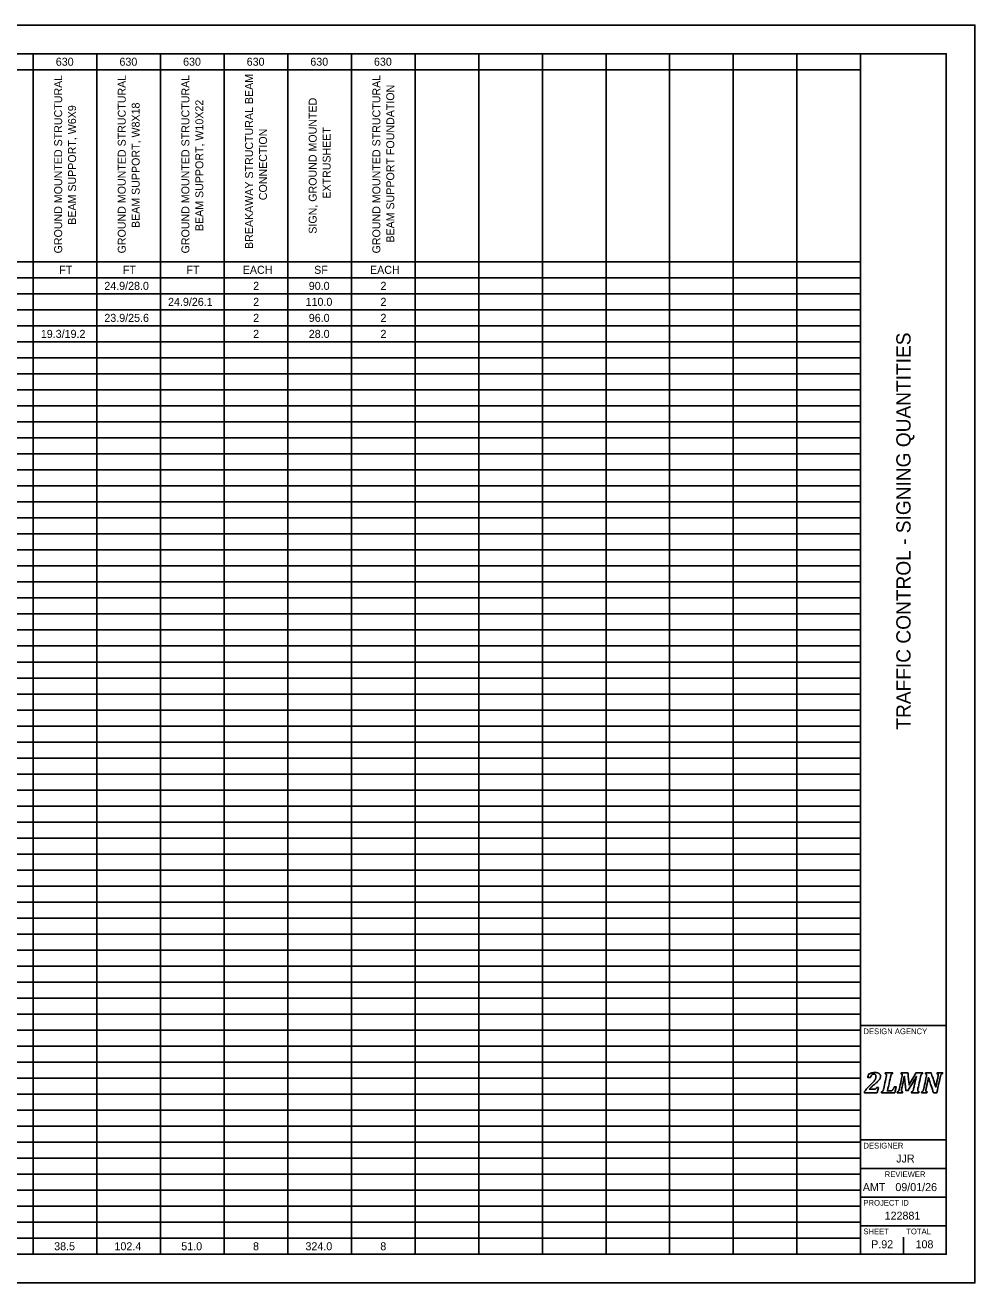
# Model space of a CAD drawing. Extents: x 0 to 34, y 0 to 22.
# Drawn here: x 17.38 to 34, y 0 to 22 of the extents above; entities that cross this region are included whole.
import ezdxf

# ---------------------------------------------------------------- set-up
doc = ezdxf.new("R2010")
doc.units = 0
for name, color, linetype in [('SH_Border', 7, 'Continuous'), ('SH_Cut_Line', 7, 'Continuous'), ('SH_Data', 7, 'Continuous'), ('SH_Text', 7, 'Continuous')]:
    doc.layers.add(name, color=color, linetype=linetype)

msp = doc.modelspace()

# ---------------------------------------------------------------- linework, layer by layer
at = {"layer": 'SH_Border'}
for p, q in [((32, 0.5), (32, 21.5)), ((32, 4.5), (33.5, 4.5)), ((32, 2.5), (33.5, 2.5)), ((32, 2), (33.5, 2)), ((32, 1.5), (33.5, 1.5)), ((32, 1), (33.5, 1))]:
    msp.add_line(p, q, dxfattribs=at)
msp.add_lwpolyline([(1.5, 21.5), (33.5, 21.5), (33.5, 0.5), (1.5, 0.5)], close=True, dxfattribs=at)
at = {"layer": 'SH_Cut_Line'}
msp.add_lwpolyline([(0, 0), (34, 0), (34, 22), (0, 22)], close=True, dxfattribs=at)
at = {"layer": 'SH_Data'}
for p, q in [((32.75, 3.5), (32.75, 3.5)), ((32.375, 0.675), (32.375, 0.675)), ((32.75, 0.5), (32.75, 0.8))]:
    msp.add_line(p, q, dxfattribs=at)
for points in [[(32.237, 3.388), (32.246, 3.388), (32.253, 3.389), (32.258, 3.39), (32.263, 3.392), (32.267, 3.394), (32.27, 3.397), (32.273, 3.401), (32.277, 3.408), (32.281, 3.417), (32.281, 3.417), (32.312, 3.417), (32.312, 3.417), (32.312, 3.417), (32.29, 3.326), (32.29, 3.326), (32.29, 3.326), (32.066, 3.326), (32.066, 3.326), (32.066, 3.326), (32.069, 3.343), (32.069, 3.343), (32.078, 3.358), (32.091, 3.375), (32.106, 3.394), (32.122, 3.412), (32.144, 3.435), (32.172, 3.462), (32.197, 3.486), (32.217, 3.506), (32.23, 3.521), (32.243, 3.537), (32.253, 3.551), (32.259, 3.566), (32.266, 3.58), (32.269, 3.595), (32.269, 3.61), (32.269, 3.622), (32.266, 3.632), (32.26, 3.64), (32.253, 3.647), (32.245, 3.65), (32.234, 3.65), (32.22, 3.65), (32.208, 3.646), (32.198, 3.636), (32.188, 3.627), (32.18, 3.613), (32.172, 3.593), (32.172, 3.593), (32.126, 3.593), (32.126, 3.593), (32.126, 3.593), (32.14, 3.654), (32.14, 3.654), (32.166, 3.663), (32.188, 3.669), (32.205, 3.673), (32.223, 3.676), (32.24, 3.678), (32.258, 3.678), (32.278, 3.678), (32.295, 3.675), (32.309, 3.669), (32.322, 3.664), (32.332, 3.656), (32.339, 3.646), (32.345, 3.637), (32.348, 3.626), (32.348, 3.613), (32.348, 3.602), (32.346, 3.591), (32.342, 3.581), (32.339, 3.571), (32.333, 3.56), (32.324, 3.549), (32.315, 3.539), (32.304, 3.526), (32.289, 3.513), (32.275, 3.499), (32.254, 3.482), (32.228, 3.46), (32.216, 3.45), (32.202, 3.438), (32.188, 3.425), (32.174, 3.412), (32.162, 3.4), (32.154, 3.391), (32.154, 3.391), (32.153, 3.388), (32.153, 3.388), (32.153, 3.388), (32.237, 3.388), (32.237, 3.388)], [(32.237, 3.388), (32.237, 3.388), (32.153, 3.388), (32.153, 3.388), (32.153, 3.388), (32.154, 3.391), (32.154, 3.391), (32.162, 3.4), (32.174, 3.412), (32.188, 3.425), (32.202, 3.438), (32.216, 3.45), (32.228, 3.46), (32.254, 3.482), (32.275, 3.499), (32.289, 3.513), (32.304, 3.526), (32.315, 3.539), (32.324, 3.549), (32.333, 3.56), (32.339, 3.571), (32.342, 3.581), (32.346, 3.591), (32.348, 3.602), (32.348, 3.613), (32.348, 3.626), (32.345, 3.637), (32.339, 3.646), (32.332, 3.656), (32.322, 3.664), (32.309, 3.669), (32.295, 3.675), (32.278, 3.678), (32.258, 3.678), (32.24, 3.678), (32.223, 3.676), (32.205, 3.673), (32.188, 3.669), (32.166, 3.663), (32.14, 3.654), (32.14, 3.654), (32.126, 3.593), (32.126, 3.593), (32.126, 3.593), (32.172, 3.593), (32.172, 3.593), (32.18, 3.613), (32.188, 3.627), (32.198, 3.636), (32.208, 3.646), (32.22, 3.65), (32.234, 3.65), (32.245, 3.65), (32.253, 3.647), (32.26, 3.64), (32.266, 3.632), (32.269, 3.622), (32.269, 3.61), (32.269, 3.595), (32.266, 3.58), (32.259, 3.566), (32.253, 3.551), (32.243, 3.537), (32.23, 3.521), (32.217, 3.506), (32.197, 3.486), (32.172, 3.462), (32.144, 3.435), (32.122, 3.412), (32.106, 3.394), (32.091, 3.375), (32.078, 3.358), (32.069, 3.343), (32.069, 3.343), (32.066, 3.326), (32.066, 3.326), (32.066, 3.326), (32.29, 3.326), (32.29, 3.326), (32.29, 3.326), (32.312, 3.417), (32.312, 3.417), (32.312, 3.417), (32.281, 3.417), (32.281, 3.417), (32.277, 3.408), (32.273, 3.401), (32.27, 3.397), (32.267, 3.394), (32.263, 3.392), (32.258, 3.39), (32.253, 3.389), (32.246, 3.388), (32.237, 3.388)], [(32.518, 3.356), (32.527, 3.356), (32.533, 3.357), (32.538, 3.358), (32.542, 3.36), (32.546, 3.362), (32.55, 3.365), (32.554, 3.368), (32.558, 3.372), (32.562, 3.377), (32.567, 3.382), (32.571, 3.388), (32.576, 3.397), (32.58, 3.405), (32.585, 3.415), (32.589, 3.427), (32.589, 3.427), (32.624, 3.427), (32.624, 3.427), (32.624, 3.427), (32.598, 3.326), (32.598, 3.326), (32.598, 3.326), (32.365, 3.326), (32.365, 3.326), (32.365, 3.326), (32.369, 3.343), (32.369, 3.343), (32.376, 3.345), (32.381, 3.348), (32.385, 3.351), (32.389, 3.355), (32.392, 3.36), (32.395, 3.366), (32.398, 3.373), (32.4, 3.382), (32.403, 3.395), (32.403, 3.395), (32.449, 3.605), (32.449, 3.605), (32.452, 3.615), (32.453, 3.625), (32.453, 3.635), (32.453, 3.642), (32.451, 3.647), (32.448, 3.651), (32.444, 3.654), (32.439, 3.656), (32.432, 3.657), (32.432, 3.657), (32.435, 3.674), (32.435, 3.674), (32.435, 3.674), (32.563, 3.674), (32.563, 3.674), (32.563, 3.674), (32.559, 3.657), (32.559, 3.657), (32.552, 3.655), (32.547, 3.652), (32.543, 3.649), (32.539, 3.645), (32.536, 3.64), (32.533, 3.634), (32.531, 3.627), (32.528, 3.618), (32.525, 3.605), (32.525, 3.605), (32.47, 3.356), (32.47, 3.356), (32.47, 3.356), (32.518, 3.356), (32.518, 3.356)], [(32.518, 3.356), (32.518, 3.356), (32.47, 3.356), (32.47, 3.356), (32.47, 3.356), (32.525, 3.605), (32.525, 3.605), (32.528, 3.618), (32.531, 3.627), (32.533, 3.634), (32.536, 3.64), (32.539, 3.645), (32.543, 3.649), (32.547, 3.652), (32.552, 3.655), (32.559, 3.657), (32.559, 3.657), (32.563, 3.674), (32.563, 3.674), (32.563, 3.674), (32.435, 3.674), (32.435, 3.674), (32.435, 3.674), (32.432, 3.657), (32.432, 3.657), (32.439, 3.656), (32.444, 3.654), (32.448, 3.651), (32.451, 3.647), (32.453, 3.642), (32.453, 3.635), (32.453, 3.625), (32.452, 3.615), (32.449, 3.605), (32.449, 3.605), (32.403, 3.395), (32.403, 3.395), (32.4, 3.382), (32.398, 3.373), (32.395, 3.366), (32.392, 3.36), (32.389, 3.355), (32.385, 3.351), (32.381, 3.348), (32.376, 3.345), (32.369, 3.343), (32.369, 3.343), (32.365, 3.326), (32.365, 3.326), (32.365, 3.326), (32.598, 3.326), (32.598, 3.326), (32.598, 3.326), (32.624, 3.427), (32.624, 3.427), (32.624, 3.427), (32.589, 3.427), (32.589, 3.427), (32.585, 3.415), (32.58, 3.405), (32.576, 3.397), (32.571, 3.388), (32.567, 3.382), (32.562, 3.377), (32.558, 3.372), (32.554, 3.368), (32.55, 3.365), (32.546, 3.362), (32.542, 3.36), (32.538, 3.358), (32.533, 3.357), (32.527, 3.356), (32.518, 3.356)], [(32.829, 3.674), (32.829, 3.674), (32.849, 3.461), (32.849, 3.461), (32.849, 3.461), (32.969, 3.674), (32.969, 3.674), (32.969, 3.674), (33.087, 3.674), (33.087, 3.674), (33.087, 3.674), (33.084, 3.657), (33.084, 3.657), (33.077, 3.655), (33.071, 3.652), (33.067, 3.649), (33.064, 3.645), (33.06, 3.64), (33.058, 3.634), (33.055, 3.627), (33.052, 3.618), (33.05, 3.605), (33.05, 3.605), (33.003, 3.395), (33.003, 3.395), (33.002, 3.39), (33.002, 3.387), (33.001, 3.384), (33.001, 3.382), (33.001, 3.379), (33, 3.376), (33, 3.373), (33, 3.369), (33, 3.365), (33, 3.358), (33.002, 3.353), (33.005, 3.349), (33.008, 3.346), (33.014, 3.344), (33.021, 3.343), (33.021, 3.343), (33.018, 3.326), (33.018, 3.326), (33.018, 3.326), (32.89, 3.326), (32.89, 3.326), (32.89, 3.326), (32.893, 3.343), (32.893, 3.343), (32.9, 3.345), (32.906, 3.348), (32.91, 3.351), (32.914, 3.355), (32.917, 3.36), (32.919, 3.366), (32.922, 3.373), (32.925, 3.382), (32.928, 3.395), (32.928, 3.395), (32.951, 3.502), (32.951, 3.502), (32.954, 3.513), (32.957, 3.529), (32.962, 3.548), (32.967, 3.568), (32.972, 3.588), (32.978, 3.609), (32.978, 3.609), (32.973, 3.609), (32.973, 3.609), (32.965, 3.594), (32.957, 3.579), (32.948, 3.563), (32.948, 3.563), (32.833, 3.364), (32.833, 3.364), (32.833, 3.364), (32.792, 3.364), (32.792, 3.364), (32.792, 3.364), (32.775, 3.518), (32.775, 3.518), (32.773, 3.537), (32.772, 3.554), (32.77, 3.569), (32.769, 3.583), (32.768, 3.597), (32.768, 3.611), (32.768, 3.611), (32.764, 3.611), (32.764, 3.611), (32.761, 3.596), (32.758, 3.578), (32.755, 3.558), (32.751, 3.538), (32.747, 3.521), (32.744, 3.507), (32.744, 3.507), (32.72, 3.395), (32.72, 3.395), (32.719, 3.39), (32.718, 3.387), (32.718, 3.384), (32.717, 3.382), (32.717, 3.379), (32.717, 3.376), (32.717, 3.373), (32.716, 3.369), (32.716, 3.365), (32.716, 3.358), (32.718, 3.353), (32.721, 3.349), (32.725, 3.346), (32.73, 3.344), (32.738, 3.343), (32.738, 3.343), (32.734, 3.326), (32.734, 3.326), (32.734, 3.326), (32.641, 3.326), (32.641, 3.326), (32.641, 3.326), (32.644, 3.343), (32.644, 3.343), (32.651, 3.345), (32.657, 3.348), (32.661, 3.351), (32.665, 3.355), (32.668, 3.36), (32.67, 3.366), (32.673, 3.373), (32.676, 3.382), (32.679, 3.395), (32.679, 3.395), (32.725, 3.605), (32.725, 3.605), (32.727, 3.615), (32.728, 3.625), (32.728, 3.635), (32.728, 3.642), (32.727, 3.647), (32.723, 3.651), (32.72, 3.654), (32.715, 3.656), (32.707, 3.657), (32.707, 3.657), (32.711, 3.674), (32.711, 3.674), (32.711, 3.674), (32.829, 3.674), (32.829, 3.674)], [(32.829, 3.674), (32.829, 3.674), (32.711, 3.674), (32.711, 3.674), (32.711, 3.674), (32.707, 3.657), (32.707, 3.657), (32.715, 3.656), (32.72, 3.654), (32.723, 3.651), (32.727, 3.647), (32.728, 3.642), (32.728, 3.635), (32.728, 3.625), (32.727, 3.615), (32.725, 3.605), (32.725, 3.605), (32.679, 3.395), (32.679, 3.395), (32.676, 3.382), (32.673, 3.373), (32.67, 3.366), (32.668, 3.36), (32.665, 3.355), (32.661, 3.351), (32.657, 3.348), (32.651, 3.345), (32.644, 3.343), (32.644, 3.343), (32.641, 3.326), (32.641, 3.326), (32.641, 3.326), (32.734, 3.326), (32.734, 3.326), (32.734, 3.326), (32.738, 3.343), (32.738, 3.343), (32.73, 3.344), (32.725, 3.346), (32.721, 3.349), (32.718, 3.353), (32.716, 3.358), (32.716, 3.365), (32.716, 3.369), (32.717, 3.373), (32.717, 3.376), (32.717, 3.379), (32.717, 3.382), (32.718, 3.384), (32.718, 3.387), (32.719, 3.39), (32.72, 3.395), (32.72, 3.395), (32.744, 3.507), (32.744, 3.507), (32.747, 3.521), (32.751, 3.538), (32.755, 3.558), (32.758, 3.578), (32.761, 3.596), (32.764, 3.611), (32.764, 3.611), (32.768, 3.611), (32.768, 3.611), (32.768, 3.597), (32.769, 3.583), (32.77, 3.569), (32.772, 3.554), (32.773, 3.537), (32.775, 3.518), (32.775, 3.518), (32.792, 3.364), (32.792, 3.364), (32.792, 3.364), (32.833, 3.364), (32.833, 3.364), (32.833, 3.364), (32.948, 3.563), (32.948, 3.563), (32.957, 3.579), (32.965, 3.594), (32.973, 3.609), (32.973, 3.609), (32.978, 3.609), (32.978, 3.609), (32.972, 3.588), (32.967, 3.568), (32.962, 3.548), (32.957, 3.529), (32.954, 3.513), (32.951, 3.502), (32.951, 3.502), (32.928, 3.395), (32.928, 3.395), (32.925, 3.382), (32.922, 3.373), (32.919, 3.366), (32.917, 3.36), (32.914, 3.355), (32.91, 3.351), (32.906, 3.348), (32.9, 3.345), (32.893, 3.343), (32.893, 3.343), (32.89, 3.326), (32.89, 3.326), (32.89, 3.326), (33.018, 3.326), (33.018, 3.326), (33.018, 3.326), (33.021, 3.343), (33.021, 3.343), (33.014, 3.344), (33.008, 3.346), (33.005, 3.349), (33.002, 3.353), (33, 3.358), (33, 3.365), (33, 3.369), (33, 3.373), (33, 3.376), (33.001, 3.379), (33.001, 3.382), (33.001, 3.384), (33.002, 3.387), (33.002, 3.39), (33.003, 3.395), (33.003, 3.395), (33.05, 3.605), (33.05, 3.605), (33.052, 3.618), (33.055, 3.627), (33.058, 3.634), (33.06, 3.64), (33.064, 3.645), (33.067, 3.649), (33.071, 3.652), (33.077, 3.655), (33.084, 3.657), (33.084, 3.657), (33.087, 3.674), (33.087, 3.674), (33.087, 3.674), (32.969, 3.674), (32.969, 3.674), (32.969, 3.674), (32.849, 3.461), (32.849, 3.461), (32.849, 3.461), (32.829, 3.674), (32.829, 3.674)], [(33.137, 3.674), (33.137, 3.674), (33.234, 3.674), (33.234, 3.674), (33.234, 3.674), (33.283, 3.53), (33.283, 3.53), (33.296, 3.49), (33.307, 3.456), (33.315, 3.426), (33.315, 3.426), (33.318, 3.426), (33.318, 3.426), (33.323, 3.455), (33.329, 3.488), (33.337, 3.523), (33.337, 3.523), (33.355, 3.605), (33.355, 3.605), (33.357, 3.615), (33.358, 3.625), (33.358, 3.635), (33.358, 3.642), (33.357, 3.647), (33.353, 3.651), (33.35, 3.654), (33.345, 3.656), (33.337, 3.657), (33.337, 3.657), (33.341, 3.674), (33.341, 3.674), (33.341, 3.674), (33.434, 3.674), (33.434, 3.674), (33.434, 3.674), (33.431, 3.657), (33.431, 3.657), (33.424, 3.655), (33.418, 3.652), (33.414, 3.649), (33.41, 3.645), (33.407, 3.64), (33.405, 3.634), (33.402, 3.627), (33.399, 3.618), (33.396, 3.605), (33.396, 3.605), (33.335, 3.326), (33.335, 3.326), (33.335, 3.326), (33.277, 3.326), (33.277, 3.326), (33.277, 3.326), (33.216, 3.504), (33.216, 3.504), (33.211, 3.518), (33.207, 3.531), (33.204, 3.543), (33.2, 3.556), (33.195, 3.571), (33.19, 3.59), (33.19, 3.59), (33.186, 3.59), (33.186, 3.59), (33.185, 3.579), (33.182, 3.563), (33.179, 3.543), (33.175, 3.523), (33.17, 3.501), (33.165, 3.478), (33.165, 3.478), (33.147, 3.395), (33.147, 3.395), (33.146, 3.39), (33.145, 3.387), (33.145, 3.384), (33.144, 3.382), (33.144, 3.379), (33.144, 3.376), (33.143, 3.373), (33.143, 3.369), (33.143, 3.365), (33.143, 3.358), (33.145, 3.353), (33.148, 3.349), (33.152, 3.346), (33.157, 3.344), (33.164, 3.343), (33.164, 3.343), (33.161, 3.326), (33.161, 3.326), (33.161, 3.326), (33.067, 3.326), (33.067, 3.326), (33.067, 3.326), (33.071, 3.343), (33.071, 3.343), (33.078, 3.345), (33.083, 3.348), (33.087, 3.351), (33.091, 3.355), (33.094, 3.36), (33.097, 3.366), (33.1, 3.373), (33.102, 3.382), (33.105, 3.395), (33.105, 3.395), (33.151, 3.605), (33.151, 3.605), (33.154, 3.615), (33.155, 3.625), (33.155, 3.635), (33.155, 3.642), (33.153, 3.647), (33.15, 3.651), (33.146, 3.654), (33.141, 3.656), (33.134, 3.657), (33.134, 3.657), (33.137, 3.674), (33.137, 3.674)], [(33.137, 3.674), (33.137, 3.674), (33.134, 3.657), (33.134, 3.657), (33.141, 3.656), (33.146, 3.654), (33.15, 3.651), (33.153, 3.647), (33.155, 3.642), (33.155, 3.635), (33.155, 3.625), (33.154, 3.615), (33.151, 3.605), (33.151, 3.605), (33.105, 3.395), (33.105, 3.395), (33.102, 3.382), (33.1, 3.373), (33.097, 3.366), (33.094, 3.36), (33.091, 3.355), (33.087, 3.351), (33.083, 3.348), (33.078, 3.345), (33.071, 3.343), (33.071, 3.343), (33.067, 3.326), (33.067, 3.326), (33.067, 3.326), (33.161, 3.326), (33.161, 3.326), (33.161, 3.326), (33.164, 3.343), (33.164, 3.343), (33.157, 3.344), (33.152, 3.346), (33.148, 3.349), (33.145, 3.353), (33.143, 3.358), (33.143, 3.365), (33.143, 3.369), (33.143, 3.373), (33.144, 3.376), (33.144, 3.379), (33.144, 3.382), (33.145, 3.384), (33.145, 3.387), (33.146, 3.39), (33.147, 3.395), (33.147, 3.395), (33.165, 3.478), (33.165, 3.478), (33.17, 3.501), (33.175, 3.523), (33.179, 3.543), (33.182, 3.563), (33.185, 3.579), (33.186, 3.59), (33.186, 3.59), (33.19, 3.59), (33.19, 3.59), (33.195, 3.571), (33.2, 3.556), (33.204, 3.543), (33.207, 3.531), (33.211, 3.518), (33.216, 3.504), (33.216, 3.504), (33.277, 3.326), (33.277, 3.326), (33.277, 3.326), (33.335, 3.326), (33.335, 3.326), (33.335, 3.326), (33.396, 3.605), (33.396, 3.605), (33.399, 3.618), (33.402, 3.627), (33.405, 3.634), (33.407, 3.64), (33.41, 3.645), (33.414, 3.649), (33.418, 3.652), (33.424, 3.655), (33.431, 3.657), (33.431, 3.657), (33.434, 3.674), (33.434, 3.674), (33.434, 3.674), (33.341, 3.674), (33.341, 3.674), (33.341, 3.674), (33.337, 3.657), (33.337, 3.657), (33.345, 3.656), (33.35, 3.654), (33.353, 3.651), (33.357, 3.647), (33.358, 3.642), (33.358, 3.635), (33.358, 3.625), (33.357, 3.615), (33.355, 3.605), (33.355, 3.605), (33.337, 3.523), (33.337, 3.523), (33.329, 3.488), (33.323, 3.455), (33.318, 3.426), (33.318, 3.426), (33.315, 3.426), (33.315, 3.426), (33.307, 3.456), (33.296, 3.49), (33.283, 3.53), (33.283, 3.53), (33.234, 3.674), (33.234, 3.674), (33.234, 3.674), (33.137, 3.674), (33.137, 3.674)]]:
    msp.add_open_spline(points, degree=3, dxfattribs=at)
at = {"layer": 'SH_Text'}
for p, q in [((1.5, 21.5), (32, 21.5)), ((17.52, 21.5), (17.52, 0.5)), ((18.634, 21.5), (18.634, 0.5)), ((19.748, 21.5), (19.748, 0.5)), ((20.861, 21.5), (20.861, 0.5)), ((21.975, 21.5), (21.975, 0.5)), ((23.089, 21.5), (23.089, 0.5)), ((24.203, 21.5), (24.203, 0.5)), ((25.317, 21.5), (25.317, 0.5)), ((26.431, 21.5), (26.431, 0.5)), ((27.545, 21.5), (27.545, 0.5)), ((28.658, 21.5), (28.658, 0.5)), ((29.772, 21.5), (29.772, 0.5)), ((30.886, 21.5), (30.886, 0.5)), ((32, 21.5), (32, 0.5)), ((10.673, 21.22), (32, 21.22)), ((10.673, 17.86), (32, 17.86)), ((1.5, 17.58), (32, 17.58)), ((1.5, 17.3), (32, 17.3)), ((1.5, 17.02), (32, 17.02)), ((1.5, 16.74), (32, 16.74)), ((1.5, 16.46), (32, 16.46)), ((1.5, 16.18), (32, 16.18)), ((1.5, 15.9), (32, 15.9)), ((1.5, 15.62), (32, 15.62)), ((1.5, 15.34), (32, 15.34)), ((1.5, 15.06), (32, 15.06)), ((1.5, 14.78), (32, 14.78)), ((1.5, 14.5), (32, 14.5)), ((1.5, 14.22), (32, 14.22)), ((1.5, 13.94), (32, 13.94)), ((1.5, 13.66), (32, 13.66)), ((1.5, 13.38), (32, 13.38)), ((1.5, 13.1), (32, 13.1)), ((1.5, 12.82), (32, 12.82)), ((1.5, 12.54), (32, 12.54)), ((1.5, 12.26), (32, 12.26)), ((1.5, 11.98), (32, 11.98)), ((1.5, 11.7), (32, 11.7)), ((1.5, 11.42), (32, 11.42)), ((1.5, 11.14), (32, 11.14)), ((1.5, 10.86), (32, 10.86)), ((1.5, 10.58), (32, 10.58)), ((1.5, 10.3), (32, 10.3)), ((1.5, 10.02), (32, 10.02)), ((1.5, 9.74), (32, 9.74)), ((1.5, 9.46), (32, 9.46)), ((1.5, 9.18), (32, 9.18)), ((1.5, 8.9), (32, 8.9)), ((1.5, 8.62), (32, 8.62)), ((1.5, 8.34), (32, 8.34)), ((1.5, 8.06), (32, 8.06)), ((1.5, 7.78), (32, 7.78)), ((1.5, 7.5), (32, 7.5)), ((1.5, 7.22), (32, 7.22)), ((1.5, 6.94), (32, 6.94)), ((1.5, 6.66), (32, 6.66)), ((1.5, 6.38), (32, 6.38)), ((1.5, 6.1), (32, 6.1)), ((1.5, 5.82), (32, 5.82)), ((1.5, 5.54), (32, 5.54)), ((1.5, 5.26), (32, 5.26)), ((1.5, 4.98), (32, 4.98)), ((1.5, 4.7), (32, 4.7)), ((1.5, 4.42), (32, 4.42)), ((1.5, 4.14), (32, 4.14)), ((1.5, 3.86), (32, 3.86)), ((1.5, 3.58), (32, 3.58)), ((1.5, 3.3), (32, 3.3)), ((1.5, 3.02), (32, 3.02)), ((1.5, 2.74), (32, 2.74)), ((1.5, 2.46), (32, 2.46)), ((1.5, 2.18), (32, 2.18)), ((1.5, 1.9), (32, 1.9)), ((1.5, 1.62), (32, 1.62)), ((1.5, 1.34), (32, 1.34)), ((1.5, 1.06), (32, 1.06)), ((1.5, 0.78), (32, 0.78)), ((1.5, 0.5), (32, 0.5))]:
    msp.add_line(p, q, dxfattribs=at)

# ---------------------------------------------------------------- texts
at = {"layer": 'SH_Data'}
msp.add_text('TRAFFIC CONTROL - SIGNING QUANTITIES', height=0.25, rotation=90, dxfattribs=at).set_placement((32.875, 9.677))
for s, height, p in [('DESIGN AGENCY', 0.1, (32.05, 4.35)), ('DESIGNER', 0.1, (32.05, 2.35)), ('JJR', 0.14, (32.624, 2.105)), ('REVIEWER', 0.1, (32.422, 1.85)), ('AMT', 0.14, (32.039, 1.605)), ('09/01/26', 0.14, (32.609, 1.605)), ('PROJECT ID', 0.1, (32.05, 1.35)), ('122881', 0.14, (32.421, 1.105)), ('SHEET', 0.1, (32.05, 0.85)), ('TOTAL', 0.1, (32.8, 0.85)), ('P.92', 0.14, (32.185, 0.605)), ('108', 0.14, (32.962, 0.605))]:
    msp.add_text(s, height=height, dxfattribs=at).set_placement(p)
at = {"layer": 'SH_Text'}
for s, p in [('630', (17.914, 21.29)), ('630', (19.028, 21.29)), ('630', (20.142, 21.29)), ('630', (21.255, 21.29)), ('630', (22.369, 21.29)), ('630', (23.483, 21.29)), ('FT', (17.974, 17.65)), ('FT', (19.088, 17.65)), ('FT', (20.201, 17.65)), ('EACH', (21.186, 17.65)), ('SF', (22.436, 17.65)), ('EACH', (23.413, 17.65)), ('24.9/28.0', (18.763, 17.37)), ('2', (21.369, 17.37)), ('90.0', (22.342, 17.37)), ('2', (23.597, 17.37)), ('24.9/26.1', (19.879, 17.09)), ('2', (21.369, 17.09)), ('110.0', (22.286, 17.09)), ('2', (23.597, 17.09)), ('23.9/25.6', (18.764, 16.81)), ('2', (21.369, 16.81)), ('96.0', (22.342, 16.81)), ('2', (23.597, 16.81)), ('19.3/19.2', (17.652, 16.53)), ('2', (21.369, 16.53)), ('28.0', (22.342, 16.53)), ('2', (23.597, 16.53)), ('38.5', (17.886, 0.57)), ('102.4', (18.941, 0.57)), ('51.0', (20.111, 0.57)), ('8', (21.366, 0.57)), ('324.0', (22.284, 0.57)), ('8', (23.594, 0.57))]:
    msp.add_text(s, height=0.14, dxfattribs=at).set_placement(p)
for s, height, p in [('GROUND MOUNTED STRUCTURAL ', 0.13923, (18.025, 18.007)), ('GROUND MOUNTED STRUCTURAL ', 0.13923, (19.138, 18.007)), ('GROUND MOUNTED STRUCTURAL ', 0.13923, (20.252, 18.007)), ('BREAKAWAY STRUCTURAL BEAM ', 0.13923, (21.366, 18.085)), ('GROUND MOUNTED STRUCTURAL ', 0.13923, (23.594, 18.007)), ('BEAM SUPPORT FOUNDATION', 0.13923, (23.838, 18.196)), ('BEAM SUPPORT, W10X22', 0.13923, (20.496, 18.398)), ('SIGN, GROUND MOUNTED ', 0.13923, (22.48, 18.352)), ('BEAM SUPPORT, W6X9', 0.13923, (18.268, 18.509)), ('BEAM SUPPORT, W8X18', 0.13923, (19.382, 18.452)), ('CONNECTION', 0.1392, (21.61, 18.938)), ('EXTRUSHEET', 0.1392, (22.724, 18.965))]:
    msp.add_text(s, height=height, rotation=90, dxfattribs=at).set_placement(p)

doc.saveas('drawing.dxf')
